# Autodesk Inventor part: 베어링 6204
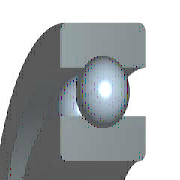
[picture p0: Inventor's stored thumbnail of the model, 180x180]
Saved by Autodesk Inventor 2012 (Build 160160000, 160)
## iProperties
IsCustomPart: 0
Created: 2009-02
Part Number: 베어링 6204
Material: 강, 연강
Description: 깊은 그루브 볼 베어링
Document SubType Name: Modeling
Standard: KS B 2023
Designer: KYOUNG IL JANG
Standards Organization: KS
Language: ko-KR
Size Designation: 6204 - 20 x 47 x 14
Categories: <MemberInstance><Categories><Category DisplayName="샤프트 부품" InternalName="7f7aeb1f-a693-4053-b835-cee3144e0d98" Mnemonic="SHFT"><Category DisplayName="베어링" Inter
Density: 7.86 g/cm^3
Mass: 104.255 g
Surface Area: 87.8912 cm^2
Volume: 13.264 cm^3
Author: KYOUNG IL JANG
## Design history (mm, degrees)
revolve "본체" stored, may be unused: angle "d6" = 90 deg
revolve "볼" stored, may be unused: angle "d7" = 90 deg
pattern_circular "IDS_ARRAYBALL[SIMPL:T]" dims angle "d3" = 360 deg
body "Solid1"
sketch "스케치" dims "d0" = 7.02 (= -0.26 x WD + 0.26 x BD)
  geometry: L1 (3.49, 16.75)-(10.51, 16.75); L2 (7, 16.75)-(7, 13.24); L3 (7, 16.75)-(7, 20.26); L4 (4.392, 14.401)-(0, 14.401); L5 (0, 10)-(14, 10); L6 (4.392, 19.099)-(0, 19.099); L7 (0, 23.5)-(14, 23.5); L8 (14, 10)-(14, 14.401); L9 (9.608, 14.401)-(14, 14.401); L10 (9.608, 19.099)-(14, 19.099); L11 (14, 23.5)-(14, 19.099); L12 (-1.4, 0)-(8.4, 0) reference; L13 (0, -0.3)-(0, 5.3) reference
  constraints: 22 end point, 4 point on line, 2 collinear, 2 perpendicular, 2 symmetric about line, 1 midpoint, 1 parallel, 14 other
  dimensions: "d9" = 20 diameter of L5 L12 (= WD); "d11" = 47 diameter of L7 L12 (= BD); "d12" = 14 distance between parallel lines of L8 L13 (= KB); "d13" = 28.802 diameter of L9 L12 (= 0.326 x BD + 0.674 x WD)
fillet "모깎기1" dims "d1" = 1 (= KRS)
other parameters: "WD" = 20 [user parameter; used in 5 equation terms], "BD" = 47 [user parameter; used in 5 equation terms], "KB" = 14 [user parameter; used in 1 equation term], "KRS" = 1 [user parameter; used in 1 equation term], "d4" = 0, "d5" = 0, "d8" = 0, "d14" = 0, "d15" = 0, "BBA" = 0 [user parameter], "BC0" = 6550000 [user parameter], "BC" = 1.27e+07 [user parameter], "BR" = 23.5 (= 0.5 x BD) [user parameter]
